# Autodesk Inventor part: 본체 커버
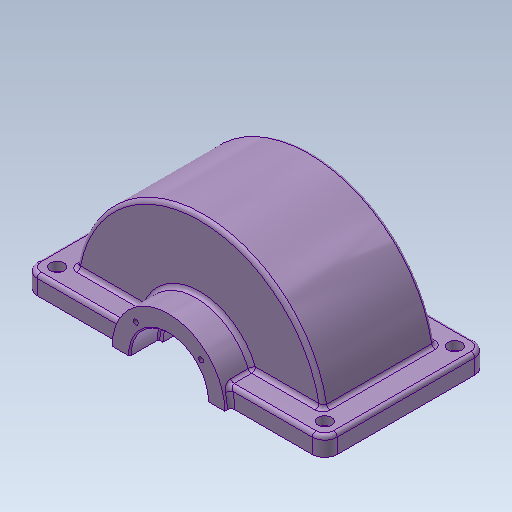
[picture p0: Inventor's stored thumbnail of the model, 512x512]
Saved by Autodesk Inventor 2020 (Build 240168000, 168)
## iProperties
Created: 2023-06
Part Number: 본체 커버
Material: 일반
Document SubType Name: Modeling
Designer: mdu-01
Density: 1 g/cm^3
Appearance: 알루미늄 - 평지(1)
Author: mdu-01
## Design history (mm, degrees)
sketch "스케치1"
  geometry: L1 (0, 70)-(0, -70); L2 (0, 70)-(45, 70); L3 (45, 70)-(45, 45); L4 (45, 45)-(100, 45); L5 (0, 0)-(100, 0); L6 (0, -70)-(45, -70); L7 (45, -70)-(45, -45); L8 (45, -45)-(100, -45); L9 (100, 45)-(100, -45); 1 further point
  constraints: 18 end point, 3 perpendicular, 3 symmetric about line, 2 midpoint, 2 parallel, 1 coincident, 1 vertical
  dimensions: "d0" = 140 distance of L1.start L1.end; "d1" = 90 diameter of L3 L1; "d2" = 90 distance between parallel lines of L8 L4; "d3" = 200 diameter of L9 L1
revolve "회전1" sketch "스케치1" stored, may be unused: angle "d4" = 180 deg
sketch "스케치2"
  geometry: L1 (-10, -110)-(210, -110); L2 (220, -100)-(220, 10); L3 (210, 20)-(-10, 20); L4 (-20, 10)-(-20, -100); L5 (-20, -110)-(220, 20); L6 (220, -110)-(-20, 20); A1 r 10 centre (-10, 10) between (-10, 20) and (-20, 10); A2 r 10 centre (210, 10) between (220, 10) and (210, 20); A3 r 10 centre (210, -100) between (210, -110) and (220, -100); A4 r 10 centre (-10, -100) between (-20, -100) and (-10, -110); 1 further point
  constraints: 12 end point, 8 point on circle, 8 point on line, 8 tangent, 4 centre point, 3 equal radius, 2 midpoint, 2 parallel, 1 horizontal, 1 perpendicular
  dimensions: "d5" = 240 distance of L6.end L5.end; "d6" = 130 distance of L5.end L6.start; "d7" = 10 radius of A1
extrude "돌출1" join sketch "스케치2" distance "d8" = 15; taper "d9" = 0 deg
sketch "스케치3"
  geometry: L1 (0, 70)-(45, 70) reference; L2 (0, -70)-(45, -70) reference; L3 (0, 70)-(0, -70); L4 (31, 70)-(31, 48); L5 (30, 47)-(27.5, 47); L6 (27.5, 47)-(27.5, 32); L7 (27.5, 32)-(87, 32); L8 (0, 0)-(92.097, 0); L9 (31, -70)-(31, -48); L10 (30, -47)-(27.5, -47); L11 (27.5, -47)-(27.5, -32); L12 (27.5, -32)-(87, -32); L13 (87, 32)-(87, -32); L14 (0, 70)-(31, 70); L15 (0, -70)-(31, -70); A1 r 1 centre (30, 48) between (30, 47) and (31, 48); A2 r 1 centre (30, -48) between (31, -48) and (30, -47); 2 further points
  constraints: 26 end point, 5 point on line, 5 symmetric about line, 4 parallel, 4 point on circle, 4 tangent, 3 perpendicular, 2 centre point, 2 collinear, 1 equal radius
  dimensions: "d10" = 1 radius of A1; "d11" = 62 diameter of L4 L3; "d12" = 23 distance between parallel lines of L1 L5; "d13" = 64 distance between parallel lines of L12 L7; "d14" = 55 diameter of L6 L3; "d15" = 87 distance between parallel lines of L13 L3
revolve "회전2" sketch "스케치3" stored, may be unused: angle "d16" = 180 deg
fillet "모깎기1" dims "d17" = 3
fillet "모깎기2" dims "d18" = 3
sketch "스케치4"
  geometry: L1 (-7, -7)-(207, -7); L2 (207, -7)-(207, 97); L3 (207, 97)-(-7, 97); L4 (-7, 97)-(-7, -7); L5 (-7, -7)-(207, 97); L6 (207, -7)-(-7, 97); 1 further point
  constraints: 12 end point, 2 midpoint, 2 parallel, 1 horizontal, 1 perpendicular
  dimensions: "d19" = 214 distance of L3.end L2.end; "d20" = 104 distance of L2.end L1.end
hole "구멍1" sketch "스케치4" at (207, -7), (-7, -7), (207, 97), (-7, 97) diameter "d21" = 6.6; stored, may be unused: countersink angle "d25" = 90 deg, drill point angle "d27" = 118 deg; dims "d22" = 6, "d23" = 11, "d24" = 6.8, "d26" = 8
sketch "스케치5"
  geometry: L1 (-26.163, 26.163)-(26.163, 26.163); L2 (26.163, 26.163)-(26.163, -26.163); L3 (26.163, -26.163)-(-26.163, -26.163); L4 (-26.163, -26.163)-(-26.163, 26.163); A1 r 37 centre (0, 0) between (-26.163, 26.163) and (26.163, -26.163); 1 further point
  constraints: 8 end point, 3 point on circle, 2 parallel, 2 perpendicular, 1 centre point, 1 coincident, 1 horizontal
  dimensions: "d28" = 74 diameter of A1
hole "구멍2" sketch "스케치5" at (-26.163, 26.163), (26.163, 26.163) diameter "d29" = 4.134; stored, may be unused: countersink angle "d33" = 90 deg, drill point angle "d35" = 118 deg; dims "d30" = 10, "d31" = 11, "d32" = 6.8, "d34" = 12
chamfer "모따기1" distance "d36" = 1; stored, may be unused: second distance "d37" = 2, angle "d38" = 45 deg
node "솔리드1"
mirror "대칭1"
